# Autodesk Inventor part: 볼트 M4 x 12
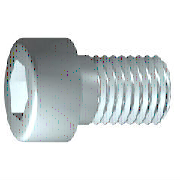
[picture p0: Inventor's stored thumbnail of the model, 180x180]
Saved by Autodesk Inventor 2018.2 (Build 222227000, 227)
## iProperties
IsCustomPart: 0
Created: 2012-02
Part Number: 볼트 M4 x 12
Material: 스테인리스강
Description: 6각 소켓 머리 캡 나사
Document SubType Name: Modeling
Standard: ISO 4762
Designer: mduedu
Standard Revision: Fourth edition 2004-03-01
Standards Organization: ISO
Language: ko-KR
Size Designation: M4 x 8
Categories: <MemberInstance><Categories><Category DisplayName="조임쇠" InternalName="e4da775c-781d-43d5-af7c-5136215cf5a6" Mnemonic="FSTN"><Category DisplayName="볼트" InternalN
Density: 8.08 g/cm^3
Mass: 2.29719 g
Surface Area: 3.30853 cm^2
Volume: 0.284306 cm^3
Appearance: 반광택
Author: mduedu
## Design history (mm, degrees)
sketch "스케치1"
  geometry: L1 (-1, 0)-(12, 0); L2 (12, 0)-(12, 2); L3 (12, 2)-(1.75, 2); L4 (1.75, 2)-(1.32, 2); L5 (1.32, 2)-(0, 2); L6 (0, 2)-(0, 3.5); L7 (0, 3.5)-(-4, 3.5); L8 (-4, 3.5)-(-4, 1.732); L9 (-4, 1.732)-(-2, 1.732); L10 (-2, 1.732)-(-1, 0); L11 (-7.2, 0)-(15.2, 0) reference; L12 (0, -0.7)-(0, 4.2) reference; L13 (1.75, 2)-(0, 2)
  constraints: 22 end point, 6 parallel, 2 collinear, 2 perpendicular, 1 horizontal, 1 point on line
  dimensions: "d1" = 10.25 distance from line of L3.end L2 (= GEL); "d2" = 0.42952 distance of L4.end L3.end (computed from GAL); "d3" = 4 distance between parallel lines of L8 L6 (= KOH); "d4" = 2 distance of L8.end L9.end (= INTI); "d5" = 60 deg angle of L10 L1; "d6" = 4 diameter of L3 L1 (= GD); "d7" = 4 diameter of L5 L1 (= BDM); "d8" = 3.4641 diameter of L9 L1 (= 1.1547 x SW); "d9" = 7 diameter of L7 L1 (= KOD); "d26" = 12 distance between parallel lines of L12 L2 (= NLG)
revolve "본체" sketch "스케치1" stored, may be unused: angle "d10" = 90 deg
sketch "스케치2"
  geometry: L1 (0, -4.9)-(0, 4.9) reference; L2 (-4.9, 0)-(4.9, 0) reference; L3 (1.732, 0)-(0.866, -1.5); L4 (0.866, -1.5)-(-0.866, -1.5); L5 (-0.866, -1.5)-(-1.732, 0); L6 (-1.732, 0)-(-0.866, 1.5); L7 (-0.866, 1.5)-(0.866, 1.5); L8 (0.866, 1.5)-(1.732, 0); 2 further points
  constraints: 12 end point, 1 coincident, 1 horizontal alignment, 1 point on line, 12 other
extrude "슬롯" join sketch "스케치2" stored distance "d11" = 10; taper "d12" = 0 deg
workplane "Work Plane1"
fillet "Fillet2" dims "d30" = 0.1 (= R)
body "Solid1"
fillet "모깎기1" dims "d17" = 0.4 (= RR)
feature "스레드" dims "d13" = 10.25 (= GEL), "d14" = 0
chamfer "모따기1" distance "d15" = 0.42941 (= -0.5 x SPD + 0.5 x GD); stored, may be unused: second distance "d16" = 0.42941 (= GUL), angle "d27" = 45 deg
other parameters: "GD" = 4 [user parameter; used in 2 equation terms], "NLG" = 12 [user parameter; used in 1 equation term], "GEL" = 10.25 [user parameter; used in 2 equation terms], "KOD" = 7 [user parameter; used in 1 equation term], "KOH" = 4 [user parameter; used in 1 equation term], "INTI" = 2 [user parameter; used in 1 equation term], "GAL" = 0.42941 (= 0.61345 x PTC) [user parameter; used in 1 equation term], "GUL" = 0.42941 (= 0.61345 x PTC) [user parameter; used in 1 equation term], "BDM" = 4 (= NND) [user parameter; used in 1 equation term], "SW" = 3 [user parameter; used in 2 equation terms], "RR" = 0.4 [user parameter; used in 1 equation term], "SPD" = 3.14117 (= NND - 1.2269 x PTC) [user parameter; used in 1 equation term], "d19" = 0, "d28" = 0, "d29" = 0, "R" = 0.1 [user parameter; used in 1 equation term], "TOA" = 30 deg [user parameter], "GD1" = 3.14117 (= THREADDIA - 1.2269 x PTC) [user parameter], "THREADDIA" = 4 [user parameter; used in 1 equation term], "FAWI" = 45 deg [user parameter], "TPU" = 14.28571 (computed from PTC) [user parameter], "PTC" = 0.7 [user parameter; used in 5 equation terms], "NND" = 4 [user parameter; used in 2 equation terms], "E0" = 3.465 (= 1.155 x SW) [user parameter]
